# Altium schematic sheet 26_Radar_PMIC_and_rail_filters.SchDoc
size 289 x 400 mm
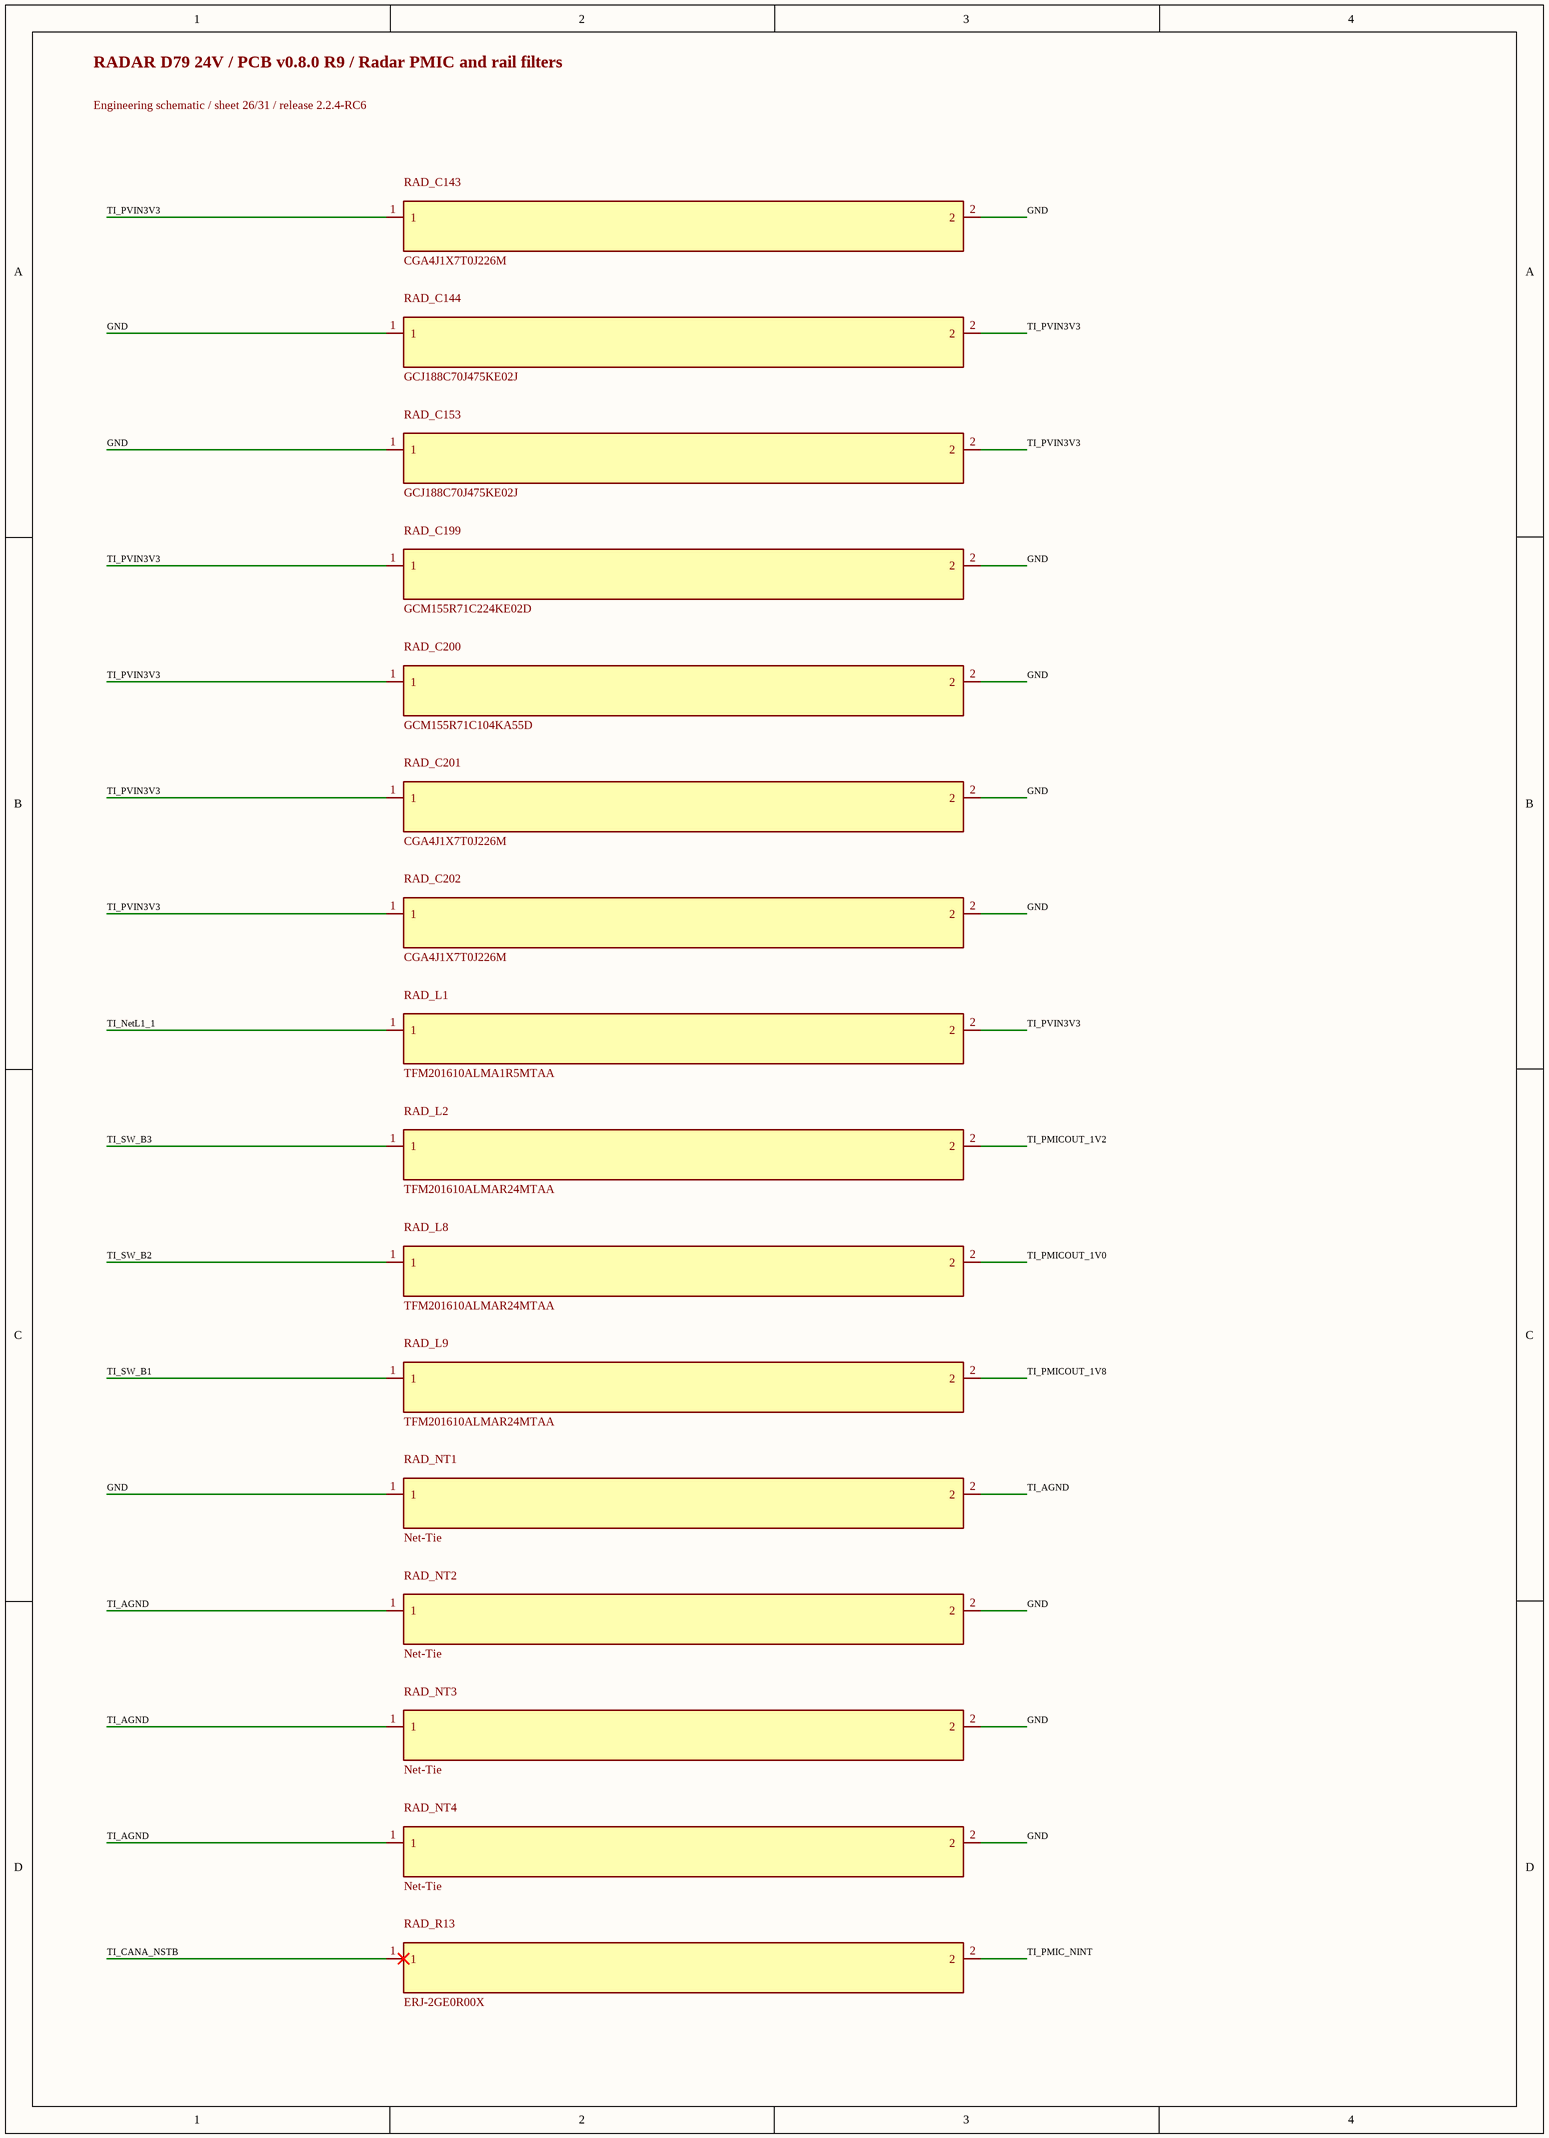
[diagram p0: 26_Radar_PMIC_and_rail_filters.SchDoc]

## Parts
RAD_C143  CGA4J1X7T0J226M  [0805_155]
RAD_C144  GCJ188C70J475KE02J  [FP-GCJ188C70J475KE02J_0603-MFG]
RAD_C153  GCJ188C70J475KE02J  [FP-GCJ188C70J475KE02J_0603-MFG]
RAD_C199  GCM155R71C224KE02D  [0402L]
RAD_C200  GCM155R71C104KA55D  [0402L]
RAD_C201  CGA4J1X7T0J226M  [0805_155]
RAD_C202  CGA4J1X7T0J226M  [0805_155]
RAD_L1  TFM201610ALMA1R5MTAA  [TFM201610ALMA]
RAD_L2  TFM201610ALMAR24MTAA  [FP-TFM201610ALMAR24MTAA_0806 (2016 Metric)-MFG]
RAD_L8  TFM201610ALMAR24MTAA  [FP-TFM201610ALMAR24MTAA_0806 (2016 Metric)-MFG]
RAD_L9  TFM201610ALMAR24MTAA  [FP-TFM201610ALMAR24MTAA_0806 (2016 Metric)-MFG]
RAD_NT1  Net-Tie  [Net-Tie_50milWide_30milLong]  (net tie, no BOM)
RAD_NT2  Net-Tie  [Net-Tie_50milWide_30milLong]  (net tie, no BOM)
RAD_NT3  Net-Tie  [Net-Tie_50milWide_30milLong]  (net tie, no BOM)
RAD_NT4  Net-Tie  [Net-Tie_50milWide_30milLong]  (net tie, no BOM)
RAD_R13  ERJ-2GE0R00X  [0402L]

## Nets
GND: RAD_C143.2 RAD_C144.1 RAD_C153.1 RAD_C199.2 RAD_C200.2 RAD_C201.2 RAD_C202.2 RAD_NT1.1 RAD_NT2.2 RAD_NT3.2 RAD_NT4.2
TI_AGND: RAD_NT1.2 RAD_NT2.1 RAD_NT3.1 RAD_NT4.1
TI_CANA_NSTB: RAD_R13.1
TI_NetL1_1: RAD_L1.1
TI_PMIC_NINT: RAD_R13.2
TI_PMICOUT_1V0: RAD_L8.2
TI_PMICOUT_1V2: RAD_L2.2
TI_PMICOUT_1V8: RAD_L9.2
TI_PVIN3V3: RAD_C143.1 RAD_C144.2 RAD_C153.2 RAD_C199.1 RAD_C200.1 RAD_C201.1 RAD_C202.1 RAD_L1.2
TI_SW_B1: RAD_L9.1
TI_SW_B2: RAD_L8.1
TI_SW_B3: RAD_L2.1

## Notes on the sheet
- RADAR D79 24V / PCB v0.8.0 R9 / Radar PMIC and rail filters
- Engineering schematic / sheet 26/31 / release 2.2.4-RC6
